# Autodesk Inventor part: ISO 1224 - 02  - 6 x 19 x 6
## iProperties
Library Location: C:\Program Files\Autodesk\Inventor 6\content
Library: local
SubLibrary: ISO
Family: 104
Member: 440
Member Major Revision: 1
Member Minor Revision: 1
Comments: To add or edit properties for Autodesk Inventor files, use iProperties.
Created: 2004-05
Part Number: ISO 1224 - 02  - 6 x 19 x 6
Vendor: Autodesk Inc.
Document SubType Name: Modeling
Designer: David
Description: Roulement à rouleaux
Standard: ISO 1224 02  - 6 x 19 x 6
Alert: To add or edit properties for Autodesk Inventor files, use iProperties.
Control State: 0
Master: False
Checked Out: False
Shininess: 64.0
Length Units: 11269
Angle Units: 11279
Time Units: 11290
Mass Units: 11283
Length Display Precision: 3
Angle Display Precision: 2
Compacted: True
Density: 0.0
Volumn: 0.0
Area: 0.0
PropertySet Name: Model Information
Author: David
Revision Number: 1
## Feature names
1. Corps [Revolution]
2. Congé1 [Fillet]
